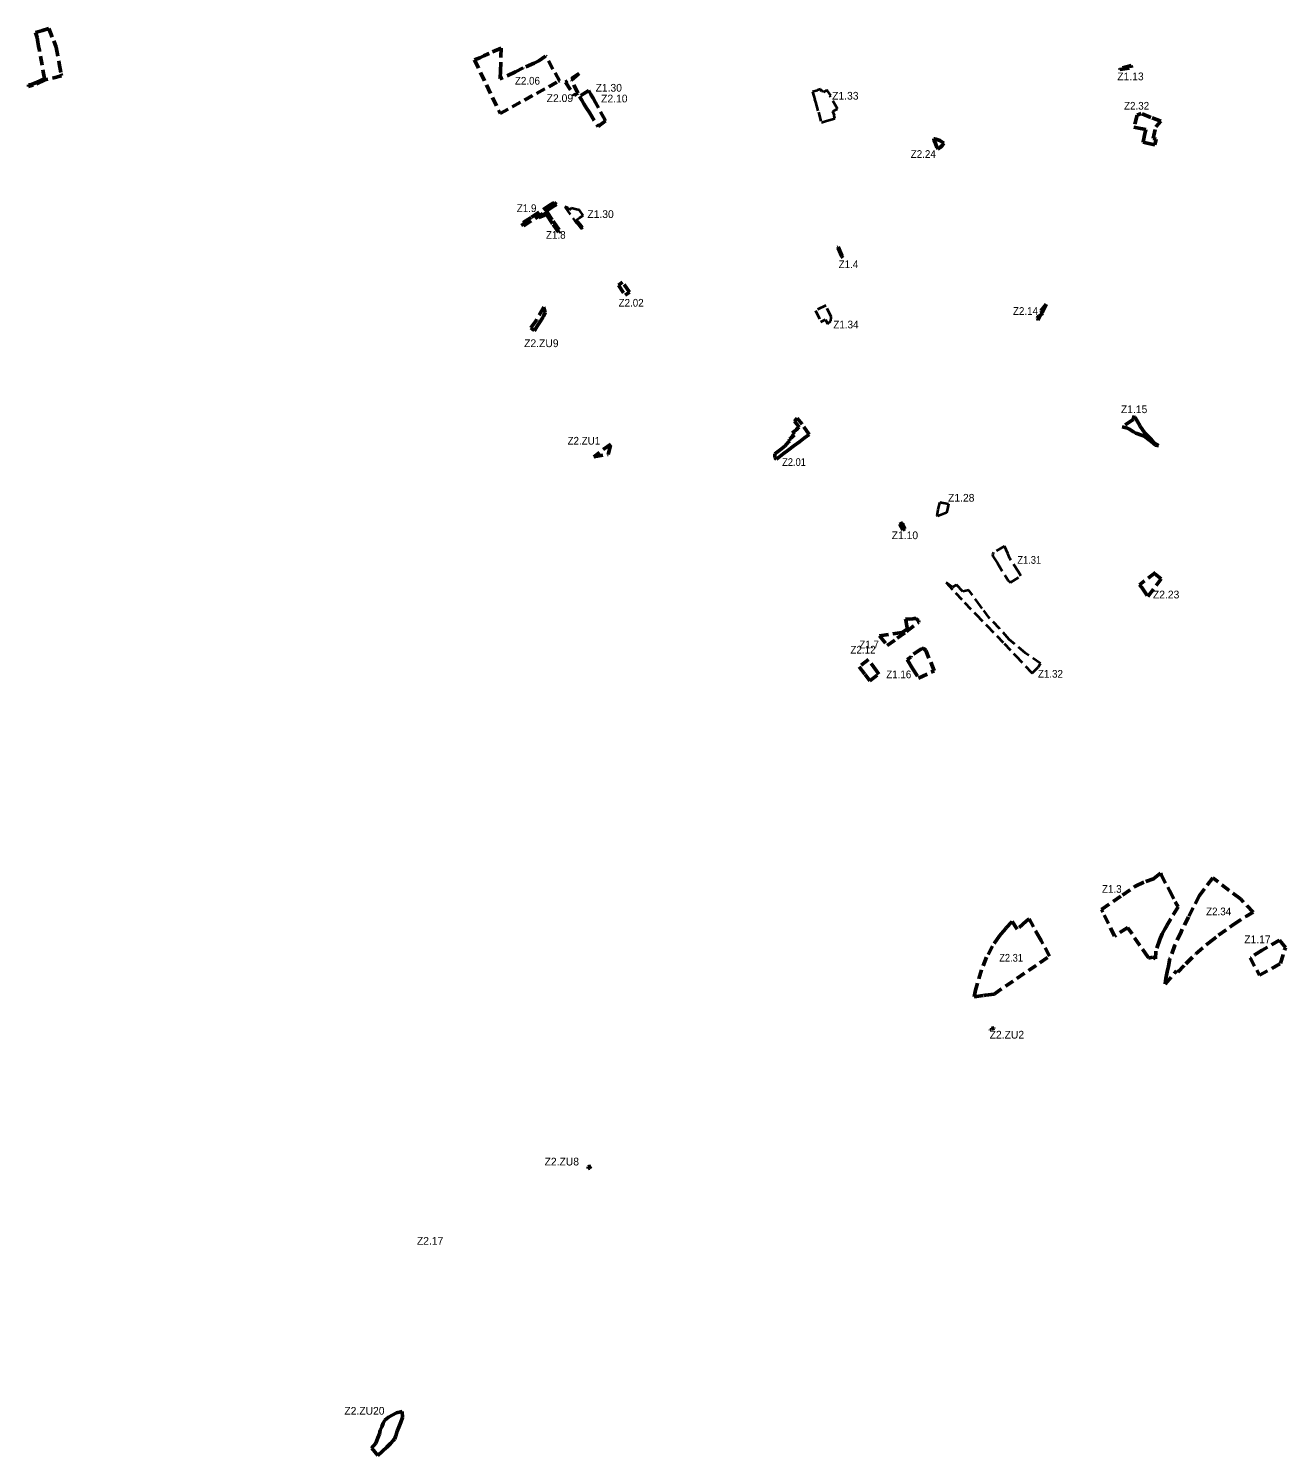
# Model space of a CAD drawing. Extents: x -650368 to -643203, y -1074215 to -1066658.
# Drawn here: x -649708 to -646290, y -1074215 to -1070336 of the extents above; entities that cross this region are included whole.
import ezdxf
from ezdxf.enums import TextEntityAlignment as Align

# ---------------------------------------------------------------- set-up
doc = ezdxf.new("R2010")
doc.units = 0
doc.header["$LTSCALE"] = 8.4
doc.linetypes.add('MEDIUM_DASHED', pattern=[4.5, 3, -1.5])
for name, color, linetype, lineweight in [('57', 7, 'MEDIUM_DASHED', 40), ('58', 7, 'MEDIUM_DASHED', 53), ('59', 7, 'MEDIUM_DASHED', 53)]:
    doc.layers.add(name, color=color, linetype=linetype, lineweight=lineweight)
for name, color, linetype in [('60', 7, 'Continuous'), ('61', 7, 'Continuous'), ('62', 7, 'Continuous')]:
    doc.layers.add(name, color=color, linetype=linetype)

msp = doc.modelspace()

# ---------------------------------------------------------------- linework, layer by layer
at = {"layer": '57', "lineweight": 53}
for points in [[(-649689.02, -1070346.94), (-649670.28, -1070341.35), (-649653.03, -1070336.2), (-649639.561, -1070370), (-649633, -1070386.46), (-649624.97, -1070431.24), (-649620.17, -1070459.09), (-649619.72, -1070461.73), (-649618.85, -1070465.12), (-649663.84, -1070475.94), (-649695.44, -1070490.03), (-649708.08, -1070493.61), (-649708.37, -1070489.38), (-649702.69, -1070488.94), (-649686.94, -1070482.59), (-649664.82, -1070473.32), (-649678.92, -1070395.81), (-649680.99, -1070384.52), (-649683.08, -1070373.11), (-649685.31, -1070360.88)], [(-646739.83, -1070444.94), (-646739.74, -1070447.98), (-646708.18, -1070442.69), (-646708.99, -1070436.76)], [(-648366.98, -1070865.44), (-648362.519, -1070872.788), (-648303.624, -1070834.844), (-648283.19, -1070821.23), (-648272.45, -1070814.075), (-648278.832, -1070808.761), (-648282.44, -1070810.84), (-648287.74, -1070814.32), (-648341.58, -1070849.98)], [(-648320.02, -1070850.16), (-648297.39, -1070835.36), (-648281.37, -1070860.23), (-648279.39, -1070862.98), (-648262.4, -1070886.58), (-648267.24, -1070889.9), (-648283.46, -1070865.74), (-648284.02, -1070864.91), (-648298.78, -1070842.92), (-648305.33, -1070843.62)], [(-647507.79, -1070930.48), (-647506.58, -1070929.86), (-647493.71, -1070959.89), (-647495.91, -1070955.93), (-647496.37, -1070956.17)], [(-647330.34, -1071678.82), (-647339.211, -1071683.431), (-647330.73, -1071700.09), (-647324.21, -1071696.2), (-647331.65, -1071681.7)], [(-647393.87, -1071987.45), (-647372.56, -1072013.58), (-647345.75, -1071993.72), (-647320.41, -1071975.27), (-647287.04, -1071950.34), (-647287.83, -1071945.52), (-647294.62, -1071939.95), (-647299.8, -1071940.18), (-647303.12, -1071940.66), (-647311.9, -1071942.01), (-647322.73, -1071940.89), (-647322.26, -1071943.87), (-647321.38, -1071949.5), (-647320.37, -1071955.14), (-647319.44, -1071960.39), (-647318.12, -1071967.77), (-647332.2, -1071978.11)], [(-646789.83, -1072730.68), (-646732.95, -1072691.68), (-646697.89, -1072667.65), (-646669.6, -1072654.53), (-646648.27, -1072647.48), (-646629.86, -1072632.07), (-646627.32, -1072636.95), (-646605.23, -1072679.37), (-646589.37, -1072709.83), (-646581.92, -1072723.91), (-646612.11, -1072774.56), (-646612.76, -1072775.67), (-646612.4, -1072775.05), (-646616.6, -1072782.31), (-646616.97, -1072782.9), (-646624.81, -1072797.42), (-646631.08, -1072812.68), (-646642.404, -1072844.195), (-646643.445, -1072864.732), (-646651.14, -1072860.57), (-646662.12, -1072863.28), (-646664.42, -1072859.9), (-646716.21, -1072783.78), (-646718.72, -1072780.09), (-646754.96, -1072803.29), (-646786.56, -1072737.88)], [(-646360.22, -1072909.57), (-646303.02, -1072877.74), (-646289.63, -1072834.04), (-646305.56, -1072814.43), (-646353.25, -1072841.63), (-646385.86, -1072862.59)]]:
    msp.add_lwpolyline(points, close=True, dxfattribs=at)
at = {"layer": '57'}
for points in [[(-647537.02, -1070503.71), (-647546, -1070508.8), (-647547.21, -1070505.8), (-647551.72, -1070507.63), (-647554.53, -1070500.69), (-647562.6, -1070503.96), (-647562.41, -1070504.46), (-647575.92, -1070508.61), (-647572.58, -1070520.08), (-647569.96, -1070529.21), (-647570.25, -1070529.29), (-647569.06, -1070533.49), (-647568.31, -1070536.13), (-647560.15, -1070563.59), (-647551.93, -1070591.24), (-647538.02, -1070587.26), (-647515.53, -1070580.81), (-647517.04, -1070572.92), (-647515.92, -1070572.48), (-647521.04, -1070561.51), (-647511.26, -1070556.25), (-647507.74, -1070554.36), (-647527.28, -1070521.45), (-647528.84, -1070518.82), (-647526.64, -1070517.92), (-647535.34, -1070505.95)], [(-648207.151, -1070878.029), (-648205.18, -1070880.5), (-648200.86, -1070877.05), (-648202.798, -1070874.754), (-648212.94, -1070862.74), (-648217.85, -1070856.93), (-648218.11, -1070856.44), (-648209.37, -1070850.44), (-648200.17, -1070844.094), (-648209.66, -1070829.88), (-648221.58, -1070827.03), (-648231.22, -1070824.92), (-648237.46, -1070829.68), (-648241.96, -1070823.46), (-648249.5, -1070821.08), (-648222.158, -1070859.221), (-648217.1, -1070865.56)], [(-647229.63, -1071623.27), (-647206.3, -1071628.17), (-647209.092, -1071641.463), (-647211.91, -1071652.25), (-647217.42, -1071654.54), (-647234.94, -1071661.83), (-647237.25, -1071659.7), (-647233.89, -1071643.39), (-647230.86, -1071629.13)], [(-647184.81, -1071848.61), (-647185.62, -1071849.12), (-647194.96, -1071854.93), (-647205.62, -1071847.24), (-647212.66, -1071842.15), (-647163.08, -1071896.13), (-647131.146, -1071929.146), (-647101.07, -1071960.24), (-647055.16, -1072007.74), (-647023.04, -1072041.63), (-646981.35, -1072085.77), (-646978.602, -1072088.66), (-646962.041, -1072072.379), (-646956.04, -1072061.95), (-646996.8, -1072034.35), (-647040.89, -1071996.58), (-647067.53, -1071967.54), (-647095.51, -1071938.39), (-647114.479, -1071912.479), (-647118.79, -1071906.59), (-647151.07, -1071863.08), (-647167.15, -1071866.22)]]:
    msp.add_lwpolyline(points, close=True, dxfattribs=at)
for points in [[(-647539.818, -1071089.2), (-647568.01, -1071102.98), (-647553.01, -1071133.68)], [(-647525.1, -1071121.25), (-647524.95, -1071119.68), (-647539.817, -1071089.199)], [(-647553.01, -1071133.68), (-647540.48, -1071127.55), (-647534.851, -1071139.015), (-647526.04, -1071130.94), (-647525.1, -1071121.25)], [(-647053.43, -1071743.63), (-647083.97, -1071760.74), (-647084.95, -1071761.98), (-647085.71, -1071763.75), (-647086.19, -1071766.95), (-647085.25, -1071770.69), (-647074.99, -1071786.99)], [(-647009.514, -1071823.81), (-647016.12, -1071813.35), (-647039.14, -1071776.9), (-647044.83, -1071763.37), (-647053.43, -1071743.63)], [(-647074.99, -1071786.99), (-647073.19, -1071789.9), (-647044.12, -1071836.68)], [(-647044.12, -1071836.68), (-647040.2, -1071839.6), (-647037.23, -1071841.82), (-647009.514, -1071823.81)]]:
    msp.add_lwpolyline(points, dxfattribs=at)
at = {"layer": '57', "lineweight": 53}
for points in [[(-646669.77, -1071438.64), (-646671.02, -1071436.82), (-646686.04, -1071415.05), (-646701.52, -1071388.41), (-646703.84, -1071399.38), (-646704.58, -1071400.2), (-646734, -1071419.27), (-646719.23, -1071422.46), (-646715.7, -1071424.14), (-646703.15, -1071432.76), (-646696.59, -1071435.91), (-646678.5, -1071442.87)], [(-646678.5, -1071442.87), (-646673.89, -1071444.28), (-646670.05, -1071447.06), (-646662.55, -1071453.44), (-646655.29, -1071458.37), (-646643.4, -1071468.99), (-646638.52, -1071470.05), (-646634.56, -1071469.49), (-646645.57, -1071462.96), (-646654.25, -1071454.23), (-646669.77, -1071438.64)], [(-647271.92, -1072022.5), (-647274.99, -1072021.69), (-647277.91, -1072021.81), (-647280.99, -1072022.86), (-647308.09, -1072041.53), (-647308.4, -1072044.8), (-647318.52, -1072051.32)], [(-647287.34, -1072101.88), (-647244.88, -1072082.33), (-647267.71, -1072027.09)], [(-647267.71, -1072027.09), (-647269.43, -1072024.67), (-647271.92, -1072022.5)], [(-647318.52, -1072051.32), (-647315.92, -1072055.47), (-647303.63, -1072075.43), (-647287.34, -1072101.88)]]:
    msp.add_lwpolyline(points, dxfattribs=at)
at = {"layer": '58'}
for points in [[(-648495.666, -1070421.476), (-648425.835, -1070567.021), (-648267.801, -1070480.55), (-648263.859, -1070478.393), (-648282.01, -1070446.35), (-648302.01, -1070411.05), (-648320.24, -1070423.64), (-648332.97, -1070430.18), (-648362.79, -1070443.63), (-648363.1, -1070443.1), (-648383.61, -1070453.86), (-648426.05, -1070473.34), (-648425.71, -1070468.87), (-648424.47, -1070452.7), (-648423.56, -1070413.35), (-648423.005, -1070389.357), (-648455.85, -1070404.19), (-648457.94, -1070405.13), (-648469.77, -1070410.47), (-648481.18, -1070415.62)], [(-648184.54, -1070505.07), (-648210.19, -1070521.07), (-648203.83, -1070531.25), (-648197.59, -1070541.27), (-648190.71, -1070552.3), (-648182.98, -1070564.68), (-648159.23, -1070602.75), (-648138.93, -1070587.1), (-648140.05, -1070585.09), (-648166.63, -1070537.28), (-648172.96, -1070525.9), (-648178.7, -1070515.58), (-648184.54, -1070505.07)], [(-646701.87, -1070603.92), (-646693.18, -1070605.83), (-646669.59, -1070611.01), (-646672.13, -1070622.41), (-646672.99, -1070626.23), (-646673.91, -1070630.38), (-646675.27, -1070636.43), (-646676.81, -1070643.36), (-646677.13, -1070644.78), (-646665.42, -1070647.54), (-646645.03, -1070652.34), (-646641.09, -1070636.89), (-646649.71, -1070634.85), (-646642.32, -1070603.3), (-646628.69, -1070588.27), (-646655.95, -1070577.64), (-646682.29, -1070567.36), (-646692.98, -1070571.45)], [(-647245.6, -1070636.4), (-647246.49, -1070638.53), (-647241.89, -1070648.94), (-647237.61, -1070658.33), (-647235.02, -1070664.1), (-647227.76, -1070658.33), (-647224.57, -1070655.48), (-647224.37, -1070655.59), (-647218.44, -1070647.43), (-647229.34, -1070640.91), (-647243.28, -1070636.43)], [(-648341.943, -1071150.071), (-648333.002, -1071157.07), (-648330.78, -1071154.36), (-648324.82, -1071145.25), (-648319.77, -1071137.52), (-648309.41, -1071121.655), (-648307.33, -1071118.47), (-648303.08, -1071108.16), (-648306.31, -1071097.36), (-648305.83, -1071096.48), (-648306.39, -1071093.99), (-648326.92, -1071128.68), (-648328.9, -1071132.02), (-648332.09, -1071136.43)], [(-646940.67, -1071085.15), (-646955.39, -1071103.23), (-646951.831, -1071107.765), (-646955.138, -1071114.466), (-646960.72, -1071117.25), (-646964.973, -1071123.095), (-646964.291, -1071125.474), (-646962.591, -1071128.96), (-646962.471, -1071129.325), (-646955.138, -1071114.466), (-646949.12, -1071111.22), (-646951.831, -1071107.765)], [(-647597.54, -1071448.75), (-647585.273, -1071440.044), (-647603.9, -1071412.1), (-647617.49, -1071394.901), (-647625.428, -1071403.267), (-647612.269, -1071419.742), (-647616.75, -1071423.83), (-647619.75, -1071426.57), (-647626.65, -1071432.87), (-647630.04, -1071435.97), (-647626.34, -1071440.73), (-647628.21, -1071443.09), (-647631.16, -1071445.79), (-647634.12, -1071448.49), (-647638.4, -1071452.55), (-647639.11, -1071452.78), (-647639.64, -1071453.33), (-647636.48, -1071457.52), (-647640.04, -1071458.97), (-647651.2, -1071471.24), (-647664.16, -1071481.45), (-647678.56, -1071492.25), (-647678.3, -1071502.55), (-647676.51, -1071504.34), (-647674.28, -1071506.59), (-647655.59, -1071492.52), (-647642.45, -1071482.62), (-647626.7, -1071470.46), (-647611.82, -1071459.38)], [(-648170.93, -1071500), (-648132.14, -1071493.74), (-648125, -1071465.96)], [(-646664.304, -1071879.909), (-646627.89, -1071832.14), (-646645.26, -1071818.72), (-646643.11, -1071814.6), (-646686.45, -1071848.26), (-646680.17, -1071856.05)], [(-647449.29, -1072071.08), (-647433.06, -1072092.41), (-647419.85, -1072109.65), (-647395.88, -1072091.34), (-647401.58, -1072082.32), (-647423.49, -1072051.76)], [(-646987.154, -1072756.377), (-646995.02, -1072762.45), (-647019.06, -1072784.57), (-647032.7, -1072763.68), (-647050.51, -1072782.79), (-647063.04, -1072796.74), (-647067.22, -1072802.77), (-647086.65, -1072830.76), (-647102.38, -1072860.7), (-647116.33, -1072895.3), (-647132.47, -1072950.4), (-647136.39, -1072968.63), (-647110.32, -1072964.56), (-647107.01, -1072964.04), (-647105.4, -1072963.84), (-647082.36, -1072960.95), (-646931.1, -1072857.55), (-646954.51, -1072815.63), (-646956.845, -1072810.746)], [(-647092.58, -1073058.59), (-647092.67, -1073058), (-647090.83, -1073057.72)], [(-647087.96, -1073056.29), (-647088.34, -1073053.92), (-647081.66, -1073052.93), (-647081.63, -1073053.13)], [(-648179.07, -1073428.81), (-648183.46, -1073429.52), (-648186.46, -1073430.01), (-648185.82, -1073435.12), (-648182.81, -1073434.38)], [(-648695.83, -1074124.88), (-648700.77, -1074138.18), (-648705.61, -1074149.4), (-648709.34, -1074161.26), (-648712.77, -1074170.51), (-648715.37, -1074173.28), (-648723.64, -1074182.09), (-648730.34, -1074189.22), (-648733.69, -1074192.38), (-648745.22, -1074203.28), (-648758.41, -1074215.05), (-648775.1, -1074194.97), (-648763.85, -1074181.6), (-648758.05, -1074167.41), (-648753.74, -1074156.28), (-648751.97, -1074146.03), (-648747.25, -1074137.56), (-648743.55, -1074127.69), (-648739.31, -1074119.01), (-648729.24, -1074110.84), (-648707.44, -1074098.79), (-648691.9, -1074095.66), (-648690.92, -1074111.64)]]:
    msp.add_lwpolyline(points, close=True, dxfattribs=at)
at = {"layer": '59'}
for points in [[(-648247.67, -1070481.57), (-648223.98, -1070518.025), (-648221.359, -1070516.349), (-648215.48, -1070512.59), (-648214.34, -1070511.86), (-648231.53, -1070476.99), (-648210.48, -1070458.42)], [(-648104.12, -1071033.78), (-648085.73, -1071060.92), (-648074.121, -1071052.749), (-648092.72, -1071025.89)], [(-646486.95, -1072644.87), (-646523.5, -1072692.86), (-646553.12, -1072751.12), (-646573.72, -1072791.74), (-646590.21, -1072827.45), (-646603.99, -1072863.84), (-646607.94, -1072885.41), (-646611.51, -1072900.28), (-646614.73, -1072918.29), (-646616.49, -1072934), (-646586.22, -1072897.88), (-646582.8, -1072901.17), (-646560.75, -1072878.59), (-646533.57, -1072851.83), (-646498.43, -1072821.57), (-646471.68, -1072801.15), (-646431.37, -1072771.48), (-646395.56, -1072748.73), (-646377.69, -1072738.13), (-646412.35, -1072701.92)]]:
    msp.add_lwpolyline(points, close=True, dxfattribs=at)

# ---------------------------------------------------------------- texts
at = {"layer": '60'}
for s, p in [('Z1.13', (-646711.241, -1070476.795)), ('Z1.30', (-648130.25, -1070507.749)), ('Z1.33', (-647486.769, -1070529.43)), ('Z1.30', (-648152.527, -1070851.191)), ('Z1.15', (-646701.349, -1071381.596)), ('Z1.28', (-647171.469, -1071622.255)), ('Z1.10', (-647324.762, -1071724.226)), ('Z1.17', (-646365.85, -1072822.584))]:
    msp.add_text(s, height=21, dxfattribs=at).set_placement(p, align=Align.CENTER)
for s, width, p in [('Z1.9', 0.95, (-648353.632, -1070835.005)), ('Z1.8', 0.95, (-648274.243, -1070907.64)), ('Z1.4', 0.95, (-647478.395, -1070987.579)), ('Z1.34', 0.95, (-647485.061, -1071151.263)), ('Z1.31', 0.9, (-646986.497, -1071791.238)), ('Z1.7', 0.95, (-647422.127, -1072021.075)), ('Z1.16', 0.95, (-647341.512, -1072102.293)), ('Z1.32', 0.95, (-646928.965, -1072100.798)), ('Z1.3', 0.95, (-646762.051, -1072685.488))]:
    msp.add_text(s, height=21, dxfattribs=dict(at, width=width)).set_placement(p, align=Align.CENTER)
at = {"layer": '61'}
for s, width, p in [('Z2.06', 0.95, (-648351.384, -1070488.722)), ('Z2.32', 0.95, (-646694.585, -1070556.682)), ('Z2.24', 0.95, (-647274.804, -1070687.883)), ('Z2.14', 0.95, (-646996.763, -1071114.597)), ('Z2.ZU1', 0.95, (-648197.892, -1071467.275)), ('Z2.01', 0.9, (-647626.341, -1071525.223)), ('Z2.12', 0.95, (-647438.697, -1072035.236)), ('Z2.31', 0.9, (-647035.914, -1072872.757))]:
    msp.add_text(s, height=21, dxfattribs=dict(at, width=width)).set_placement(p, align=Align.CENTER)
for s, p in [('Z2.10', (-648115.069, -1070536.986)), ('Z2.ZU9', (-648313.517, -1071202.172)), ('Z2.23', (-646614.24, -1071885.289)), ('Z2.ZU2', (-647047.431, -1073081.819)), ('Z2.ZU8', (-648257.993, -1073426.743)), ('Z2.ZU20', (-648794.75, -1074104.169))]:
    msp.add_text(s, height=21, dxfattribs=at).set_placement(p, align=Align.CENTER)
at = {"layer": '62'}
for s, p in [('Z2.09', (-648263.112, -1070535.96)), ('Z2.17', (-648616.086, -1073642.104))]:
    msp.add_text(s, height=21, dxfattribs=at).set_placement(p, align=Align.CENTER)
at = {"layer": '62', "width": 0.95}
for s, p in [('Z2.02', (-648069.383, -1071092.212)), ('Z2.34', (-646471.455, -1072746.692))]:
    msp.add_text(s, height=21, dxfattribs=at).set_placement(p, align=Align.CENTER)

doc.saveas('drawing.dxf')
